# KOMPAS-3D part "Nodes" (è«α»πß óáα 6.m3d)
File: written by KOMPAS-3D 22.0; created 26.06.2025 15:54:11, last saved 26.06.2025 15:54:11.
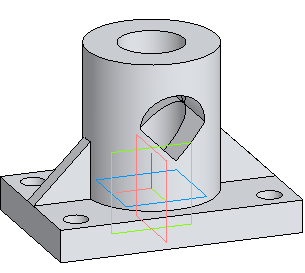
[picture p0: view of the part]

Document properties: Автор: Helen; Полное имя файла: D:\MY\WORK\MPEI\ППЭ_2025-2026\Варианты\Вар 6 СБ\Корпус вар 6.m3d

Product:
- Part/product: Nodes

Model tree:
1. Операция без истории:1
